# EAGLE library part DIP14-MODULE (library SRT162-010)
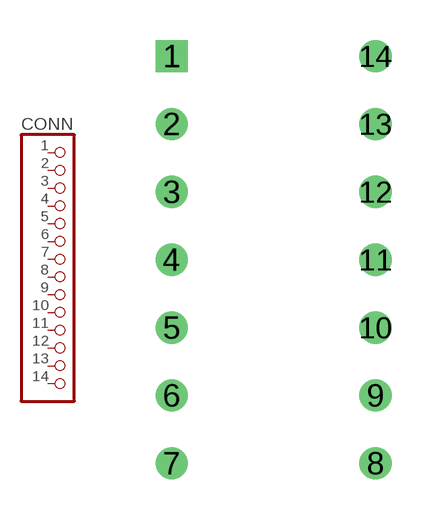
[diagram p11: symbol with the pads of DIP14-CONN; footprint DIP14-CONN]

Designator prefix CONN

## DIP14-MODULE  [DIP14-CONN]
1  1  pas
2  2  pas
3  3  pas
4  4  pas
5  5  pas
6  6  pas
7  7  pas
8  8  pas
9  9  pas
10  10  pas
11  11  pas
12  12  pas
13  13  pas
14  14  pas

## Footprint DIP14-CONN (pad centres in mm)
drill 0.7 square: 1 -3.81,7.62
drill 0.7 round: 2 -3.81,5.08; 3 -3.81,2.54; 4 -3.81,0; 5 -3.81,-2.54; 6 -3.81,-5.08; 7 -3.81,-7.62; 8 3.81,-7.62; 9 3.81,-5.08; 10 3.81,-2.54; 11 3.81,0; 12 3.81,2.54; 13 3.81,5.08; 14 3.81,7.62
